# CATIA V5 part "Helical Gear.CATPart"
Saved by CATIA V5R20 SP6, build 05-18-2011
Part number: Helical Gear
Source: made
Material "Aucun"
Bounding box of the stored display mesh (mm): x -17.969 to 17.969, y -17.991 to 17.991, z -6 to 22
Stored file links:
  E:\#01 CATIA Lecture Materials\#06 DMU\#06 DMU Page01 KIN EX06\Helical Gear.CATPart
  C:\Program Files\Dassault Systemes\B20\win_b64\startup\materials\French\Catalog.CATMaterial
  C:\usr\gt1\projet\valve\doc\doc_2005\comp\gears\bevel_gear_files\bevel_gear.CATPart
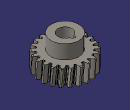
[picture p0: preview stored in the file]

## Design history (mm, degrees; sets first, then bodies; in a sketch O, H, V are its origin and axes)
Body1 (main body)
  Solid1: solid without history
